// Mitsubishi GX Works2 project: 32.8按钮单键控制，互锁（逻辑指令）   PLC: FX3U/FX3UC

PROGRAM MAIN
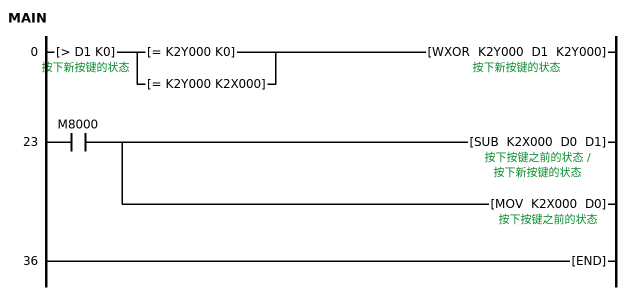
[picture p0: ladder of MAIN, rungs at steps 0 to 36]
0     LD>     D1 K0  ; 按下新按键的状态
      LD=     K2Y000 K0
      OR=     K2Y000 K2X000
      ANB
      WXOR    K2Y000 D1 K2Y000
        [note] K2Y0=0时，只有工作的Y0可操作
23    LD      M8000
      SUB     K2X000 D0 D1  ; 按下按键之前的状态
      MOV     K2X000 D0
36    END
END_PROGRAM
